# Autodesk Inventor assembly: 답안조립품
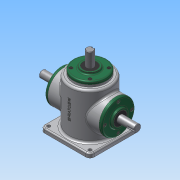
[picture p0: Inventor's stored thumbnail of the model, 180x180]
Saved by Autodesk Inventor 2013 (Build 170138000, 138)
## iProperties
Created: 2015-10
Part Number: 답안조립품
Document SubType Name: Assembly
Designer: Administrator
Author: Administrator
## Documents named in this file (14)
- C:\Users\Administrator\Desktop\451008V1023\답안조립품.iam
- C:\Users\Administrator\Desktop\451008V1023\본체.ipt
- C:\Users\Administrator\Desktop\451008V1023\베어링 6203.ipt
- C:\Users\Administrator\Desktop\451008V1023\커버.ipt
- C:\Users\Administrator\Desktop\451008V1023\오일실.ipt
- C:\Users\Administrator\Desktop\451008V1023\M4.ipt
- C:\Users\Administrator\Desktop\451008V1023\메인 축.ipt
- 메인 축.ipt
- C:\Users\Administrator\Desktop\451008V1023\키 5x5.ipt
- C:\Users\Administrator\Desktop\451008V1023\메인 베벨기어.ipt
- C:\Users\Administrator\Desktop\451008V1023\서브 축.ipt
- 서브 축.ipt
- C:\Users\Administrator\Desktop\451008V1023\키 4x4.ipt
- C:\Users\Administrator\Desktop\451008V1023\서브 베벨기어.ipt
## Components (12 placed, 1 different names)
1. M4:1
2. M4:2
3. M4:3
4. M4:4
5. M4:5
6. M4:6
7. M4:7
8. M4:8
9. M4:9
10. M4:10
11. M4:11
12. M4:12
